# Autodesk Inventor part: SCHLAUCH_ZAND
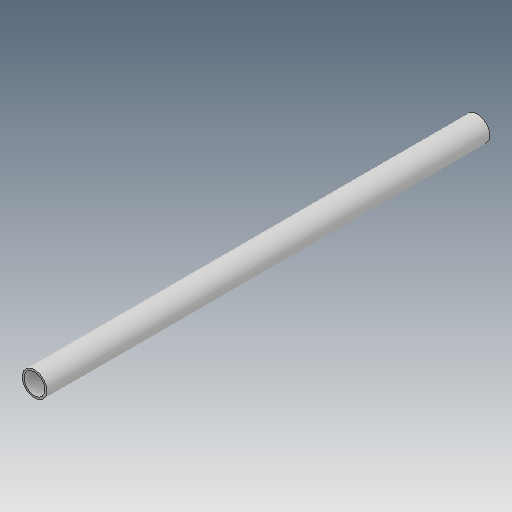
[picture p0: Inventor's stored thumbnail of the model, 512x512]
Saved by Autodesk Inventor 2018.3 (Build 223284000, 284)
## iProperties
Created: 2019-01
Part Number: SCHLAUCH_ZAND
Material: Generisch
Document SubType Name: Modeling
Designer: zand
Density: 1 g/cm^3
Appearance: Vorgabe
Mass: 3.92306 g
Surface Area: 105.051 cm^2
Volume: 3.92306 cm^3
Author: zand
Revision Number: 5LAST_VERSION
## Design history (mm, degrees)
feature "Basis1"
node "Volumenkörper1"
